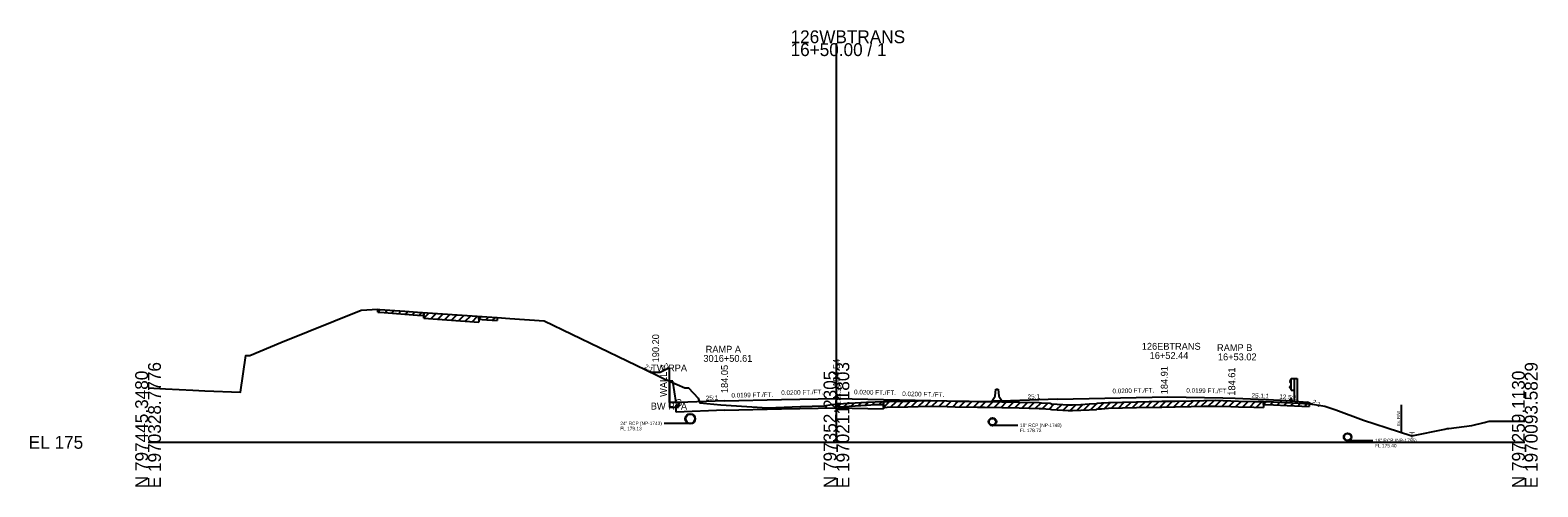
# Model space of a CAD drawing. Extents: x -6494 to 1970605, y -10 to 798140.
# Drawn here: x -25.7 to 302.8, y 8990.3 to 9089.8 of the extents above; entities that cross this region are included whole.
import ezdxf

# ---------------------------------------------------------------- set-up
doc = ezdxf.new("R2010")
doc.units = 0
for name, color, linetype in [('Default', 7, 'Continuous'), ('RD_EX_SU_Misc_TxCode', 7, 'Continuous'), ('RD_GPK_XS_Cell', 7, 'Continuous'), ('RD_Sketch1', 7, 'Continuous'), ('RD_XS_Base', 7, 'Continuous'), ('RD_XS_Box', 7, 'Continuous'), ('RD_XS_CurbTop', 7, 'Continuous'), ('RD_XS_EarthShd', 7, 'Continuous'), ('RD_XS_EwShp', 7, 'Continuous'), ('RD_XS_ExGround', 7, 'Continuous'), ('RD_XS_ExPaveRet', 7, 'Continuous'), ('RD_XS_ExRW', 7, 'Continuous'), ('RD_XS_GR', 7, 'Continuous'), ('RD_XS_MedBWall', 7, 'Continuous'), ('RD_XS_Misc_Line', 7, 'Continuous'), ('RD_XS_Pave', 7, 'Continuous'), ('RD_XS_PaveOvlay', 7, 'Continuous'), ('RD_XS_PaveShd', 7, 'Continuous'), ('RD_XS_Pipe', 7, 'Continuous'), ('RD_XS_TieSlope', 7, 'Continuous'), ('RD_XS_TX_Elev_EX', 7, 'Continuous'), ('RD_XS_TX_Elev_PR', 7, 'Continuous'), ('RD_XS_TX_Misc', 7, 'Continuous'), ('RD_XS_TX_Notes', 7, 'Continuous'), ('RD_XS_TX_Profile', 7, 'Continuous'), ('RD_XS_TX_ShdSlope', 7, 'Continuous'), ('RD_XS_TX_Slope', 7, 'Continuous'), ('RD_XS_TX_Station', 7, 'Continuous')]:
    doc.layers.add(name, color=color, linetype=linetype)

msp = doc.modelspace()

# ---------------------------------------------------------------- linework, layer by layer
at = {"layer": 'Default'}
for p, q in [((184, 9009.2), (184.58, 9010.03)), ((184, 9008.95), (184, 9009.2)), ((186, 9008.95), (184, 9008.95)), ((184.58, 9010.03), (184.75, 9011.61)), ((184.75, 9011.61), (185.25, 9011.61)), ((185.25, 9011.61), (185.42, 9010.03)), ((185.42, 9010.03), (186, 9009.2)), ((186, 9009.2), (186, 9008.95))]:
    msp.add_line(p, q, dxfattribs=at)
at = {"layer": 'RD_GPK_XS_Cell'}
for p, q in [((150, 9000), (150, 9086.93)), ((0, 9000), (150, 9000)), ((150, 9000), (300, 9000))]:
    msp.add_line(p, q, dxfattribs=at)
at = {"layer": 'RD_XS_Base'}
for p, q in [((115.61, 9008.09), (115.61, 9008.65)), ((246.93, 9008.72), (246.93, 9009.21)), ((115.11, 9008.07), (115.61, 9008.09)), ((115.11, 9006.59), (115.11, 9008.07)), ((125.62, 9007.01), (115.11, 9006.59)), ((125.62, 9007.01), (138, 9007.26)), ((138, 9007.26), (150, 9007.5)), ((150, 9007.5), (160.27, 9007.3))]:
    msp.add_line(p, q, dxfattribs=at)
at = {"layer": 'RD_XS_Box'}
for p, q in [((113.61, 9008.65), (113.61, 9016.2)), ((115.61, 9008.65), (113.61, 9008.65))]:
    msp.add_line(p, q, dxfattribs=at)
at = {"layer": 'RD_XS_CurbTop'}
for p, q in [((248.81, 9009.06), (249.06, 9009.52)), ((248.81, 9009.06), (249.27, 9009.03)), ((249.27, 9009.03), (249.21, 9009.46))]:
    msp.add_line(p, q, dxfattribs=at)
msp.add_ellipse((249.13, 9009.44), major_axis=(0, -0.131), ratio=0.686, start_param=1.762783, end_param=4.036677, dxfattribs=at)
at = {"layer": 'RD_XS_EarthShd'}
msp.add_line((246.93, 9009.21), (248.93, 9009.05), dxfattribs=at)
at = {"layer": 'RD_XS_ExGround'}
msp.add_lwpolyline([(0, 9011.84), (3.82, 9011.65), (9.76, 9011.34), (12.4, 9011.23), (20.16, 9010.91), (21.3, 9018.88), (22.14, 9018.9), (28.91, 9021.74), (46.44, 9028.78), (50.07, 9028.98), (50.5, 9028.94), (55.98, 9028.55), (58.71, 9028.36), (72.8, 9027.38), (73.79, 9027.31), (76.09, 9027.17), (78.84, 9026.97), (86.32, 9026.45), (110.4, 9014.85), (112.75, 9013.68), (113.07, 9013.58), (113.6, 9013.35), (116.99, 9011.89), (117.75, 9011.89), (119.86, 9009.65), (120.25, 9008.58), (124.78, 9008.19), (134.97, 9007.51), (142.2, 9007.8), (147.25, 9007.97), (148.99, 9008.22), (150.27, 9008.38), (156.55, 9008.72), (158.43, 9008.83), (161.04, 9008.88), (165.55, 9008.96), (167.83, 9009.02), (170.58, 9009.1), (174.13, 9009.03), (175.87, 9009), (180.71, 9008.91), (182.24, 9008.89), (189.82, 9008.74), (194.21, 9008.65), (194.68, 9008.62), (196.57, 9008.5), (196.85, 9008.39), (199.32, 9008.24), (200.48, 9008.17), (201.45, 9008.2), (203.22, 9008.27), (205.05, 9008.36), (206.64, 9008.43), (206.88, 9008.53), (207.74, 9008.58), (209.3, 9008.66), (215.42, 9008.8), (220.87, 9008.93), (223.84, 9008.99), (227.32, 9009.05), (230.08, 9009.11), (232.57, 9009.15), (235.96, 9009.05), (237.58, 9009), (240.96, 9008.91), (245.27, 9008.8), (248.2, 9008.65), (253.03, 9008.42), (254.17, 9008.24), (256.42, 9007.87), (258.82, 9007.08), (264.87, 9004.83), (272.44, 9002.37), (275.35, 9001.43), (282.56, 9002.88), (283.11, 9002.98), (283.45, 9003.02), (288.47, 9003.68), (291.12, 9004.33), (292.24, 9004.58), (300, 9004.58)], dxfattribs=at)
at = {"layer": 'RD_XS_ExPaveRet'}
for p, q in [((50.07, 9028.35), (50.07, 9028.98)), ((50.07, 9028.35), (50.5, 9028.32)), ((50.5, 9028.32), (55.98, 9027.92)), ((60.1, 9027.01), (60.1, 9028.26)), ((60.1, 9028.26), (60.1, 9027.64)), ((55.98, 9027.92), (58.71, 9027.73)), ((58.71, 9027.73), (60.1, 9027.64)), ((60.1, 9027.01), (72.08, 9026.18)), ((72.08, 9027.43), (72.08, 9026.18)), ((72.08, 9026.81), (72.08, 9027.43)), ((72.08, 9026.81), (72.8, 9026.76)), ((72.8, 9026.76), (73.79, 9026.69)), ((73.79, 9026.69), (76.09, 9026.54)), ((76.09, 9027.17), (76.09, 9026.54)), ((150.27, 9007.76), (150.27, 9008.38)), ((160.27, 9007.61), (160.27, 9008.86)), ((160.27, 9008.86), (160.27, 9008.24)), ((243.03, 9008.86), (243.03, 9007.61)), ((243.03, 9008.23), (243.03, 9008.86)), ((253.03, 9008.42), (253.03, 9007.79)), ((150.27, 9007.76), (156.55, 9008.1)), ((156.55, 9008.1), (158.43, 9008.21)), ((158.43, 9008.21), (160.27, 9008.24)), ((160.27, 9007.61), (161.04, 9007.63)), ((161.04, 9007.63), (165.55, 9007.71)), ((165.55, 9007.71), (167.83, 9007.77)), ((167.83, 9007.77), (170.58, 9007.85)), ((170.58, 9007.85), (174.13, 9007.78)), ((174.13, 9007.78), (175.87, 9007.75)), ((175.87, 9007.75), (180.71, 9007.66)), ((180.71, 9007.66), (182.24, 9007.64)), ((182.24, 9007.64), (189.82, 9007.49)), ((189.82, 9007.49), (194.21, 9007.4)), ((194.21, 9007.4), (194.68, 9007.37)), ((194.68, 9007.37), (196.57, 9007.25)), ((196.57, 9007.25), (196.85, 9007.14)), ((196.85, 9007.14), (199.32, 9006.99)), ((199.32, 9006.99), (200.48, 9006.92)), ((200.48, 9006.92), (201.45, 9006.95)), ((201.45, 9006.95), (203.22, 9007.02)), ((203.22, 9007.02), (205.05, 9007.11)), ((205.05, 9007.11), (206.64, 9007.18)), ((206.64, 9007.18), (206.88, 9007.28)), ((206.88, 9007.28), (207.74, 9007.33)), ((207.74, 9007.33), (209.3, 9007.41)), ((209.3, 9007.41), (215.42, 9007.55)), ((215.42, 9007.55), (220.87, 9007.68)), ((220.87, 9007.68), (223.84, 9007.74)), ((223.84, 9007.74), (227.32, 9007.8)), ((227.32, 9007.8), (230.08, 9007.86)), ((230.08, 9007.86), (232.57, 9007.9)), ((232.57, 9007.9), (235.96, 9007.8)), ((235.96, 9007.8), (237.58, 9007.75)), ((237.58, 9007.75), (240.96, 9007.66)), ((240.96, 9007.66), (243.03, 9007.61)), ((243.03, 9008.23), (245.27, 9008.17)), ((245.27, 9008.17), (248.2, 9008.03)), ((248.2, 9008.03), (253.03, 9007.79))]:
    msp.add_line(p, q, dxfattribs=at)
at = {"layer": 'RD_XS_ExRW'}
msp.add_line((273.04, 9008.17), (273.04, 9002.17), dxfattribs=at)
at = {"layer": 'RD_XS_GR'}
for p, q in [((249.08, 9013.77), (248.81, 9013.33)), ((248.81, 9013.33), (248.81, 9013.22)), ((248.81, 9013.22), (249.08, 9012.78)), ((248.81, 9012.07), (249.08, 9012.51)), ((248.81, 9011.96), (248.81, 9012.07)), ((249.08, 9011.52), (248.81, 9011.96)), ((249.08, 9013.93), (249.74, 9013.93)), ((249.08, 9011.36), (249.08, 9013.93)), ((249.74, 9013.93), (250.41, 9013.93)), ((249.74, 9013.93), (249.74, 9008.99)), ((250.41, 9013.93), (250.41, 9008.88)), ((249.08, 9011.36), (249.74, 9011.36))]:
    msp.add_line(p, q, dxfattribs=at)
at = {"layer": 'RD_XS_MedBWall'}
for p, q in [((114.36, 9013.32), (113.61, 9013.32)), ((113.61, 9013.32), (113.61, 9007.65)), ((115.11, 9008.65), (114.36, 9013.32)), ((115.61, 9008.65), (115.11, 9008.65)), ((115.61, 9007.65), (115.61, 9008.65)), ((113.61, 9007.65), (115.61, 9007.65))]:
    msp.add_line(p, q, dxfattribs=at)
at = {"layer": 'RD_XS_Misc_Line'}
for p, q in [((50.07, 9028.35), (50.65, 9028.93)), ((51.57, 9028.24), (52.16, 9028.82)), ((53.08, 9028.13), (53.66, 9028.72)), ((54.58, 9028.02), (55.17, 9028.61)), ((56.09, 9027.91), (56.68, 9028.5)), ((57.59, 9027.81), (58.18, 9028.39)), ((59.1, 9027.71), (59.69, 9028.29)), ((60.1, 9027.01), (61.27, 9028.18)), ((61.61, 9026.91), (62.78, 9028.08)), ((63.11, 9026.8), (64.28, 9027.97)), ((64.62, 9026.7), (65.79, 9027.87)), ((66.12, 9026.59), (67.29, 9027.76)), ((67.63, 9026.49), (68.8, 9027.66)), ((69.13, 9026.39), (70.3, 9027.55)), ((70.64, 9026.28), (71.81, 9027.45)), ((72.08, 9026.81), (72.67, 9027.39)), ((73.59, 9026.7), (74.18, 9027.29)), ((75.09, 9026.61), (75.68, 9027.19)), ((150.27, 9007.76), (150.94, 9008.42)), ((151.78, 9007.84), (152.44, 9008.5)), ((153.28, 9007.92), (153.95, 9008.58)), ((154.79, 9008), (155.45, 9008.67)), ((156.29, 9008.09), (156.96, 9008.75)), ((157.8, 9008.17), (158.46, 9008.83)), ((159.3, 9008.22), (159.94, 9008.86)), ((160.27, 9007.61), (161.55, 9008.89)), ((161.78, 9007.64), (163.06, 9008.91)), ((163.29, 9007.67), (164.56, 9008.94)), ((164.79, 9007.69), (166.07, 9008.97)), ((166.3, 9007.73), (167.59, 9009.02)), ((167.8, 9007.77), (169.09, 9009.06)), ((169.31, 9007.81), (170.59, 9009.1)), ((170.81, 9007.84), (172.04, 9009.07)), ((172.32, 9007.82), (173.55, 9009.04)), ((173.82, 9007.79), (175.05, 9009.02)), ((175.33, 9007.76), (176.56, 9008.99)), ((176.83, 9007.73), (178.06, 9008.96)), ((178.34, 9007.71), (179.57, 9008.93)), ((179.84, 9007.68), (181.07, 9008.91)), ((181.35, 9007.65), (182.58, 9008.88)), ((182.85, 9007.62), (184.08, 9008.85)), ((184.36, 9007.59), (185.59, 9008.82)), ((185.86, 9007.56), (187.09, 9008.79)), ((187.37, 9007.53), (188.6, 9008.76)), ((188.87, 9007.5), (190.1, 9008.73)), ((190.38, 9007.47), (191.61, 9008.7)), ((191.88, 9007.45), (193.11, 9008.67)), ((193.39, 9007.42), (194.6, 9008.63)), ((194.89, 9007.36), (196.07, 9008.54)), ((203.92, 9007.05), (205.24, 9008.36)), ((205.43, 9007.12), (206.82, 9008.51)), ((206.93, 9007.29), (208.26, 9008.6)), ((208.44, 9007.36), (209.75, 9008.67)), ((209.94, 9007.42), (211.23, 9008.7)), ((211.45, 9007.46), (212.73, 9008.74)), ((212.95, 9007.49), (214.24, 9008.77)), ((214.46, 9007.53), (215.74, 9008.81)), ((215.96, 9007.56), (217.25, 9008.85)), ((217.47, 9007.6), (218.76, 9008.88)), ((218.97, 9007.64), (220.26, 9008.92)), ((220.48, 9007.67), (221.76, 9008.95)), ((221.98, 9007.7), (223.26, 9008.98)), ((223.49, 9007.73), (224.77, 9009)), ((225, 9007.76), (226.27, 9009.03)), ((226.5, 9007.78), (227.78, 9009.06)), ((228.01, 9007.81), (229.29, 9009.09)), ((229.51, 9007.84), (230.79, 9009.12)), ((231.02, 9007.87), (232.29, 9009.14)), ((232.52, 9007.9), (233.74, 9009.11)), ((234.03, 9007.86), (235.24, 9009.07)), ((235.53, 9007.81), (236.75, 9009.02)), ((237.04, 9007.77), (238.26, 9008.98)), ((238.54, 9007.73), (239.76, 9008.94)), ((240.05, 9007.69), (241.27, 9008.9)), ((241.55, 9007.65), (242.77, 9008.86)), ((243.03, 9008.23), (243.64, 9008.84)), ((244.53, 9008.19), (245.15, 9008.8)), ((246.04, 9008.13), (246.64, 9008.73)), ((247.54, 9008.06), (248.14, 9008.66)), ((249.05, 9007.99), (249.65, 9008.58)), ((250.55, 9007.91), (251.15, 9008.51)), ((252.06, 9007.84), (252.66, 9008.44)), ((196.4, 9007.27), (197.48, 9008.35)), ((197.9, 9007.07), (199.09, 9008.25)), ((199.41, 9006.98), (200.6, 9008.17)), ((200.91, 9006.93), (202.21, 9008.23)), ((202.42, 9006.99), (203.73, 9008.29))]:
    msp.add_line(p, q, dxfattribs=at)
at = {"layer": 'RD_XS_Pave'}
for p, q in [((125.62, 9009.05), (138, 9009.3)), ((138, 9009.3), (150, 9009.54)), ((150, 9009.54), (174, 9009.06)), ((198.18, 9009.43), (222.19, 9009.91)), ((222.19, 9009.91), (234.19, 9009.67)), ((234.19, 9009.67), (236.9, 9009.61))]:
    msp.add_line(p, q, dxfattribs=at)
at = {"layer": 'RD_XS_PaveOvlay'}
for p, q in [((160.27, 9008.86), (161.04, 9008.88)), ((160.27, 9008.86), (160.27, 9007.3)), ((161.04, 9008.88), (165.55, 9008.96)), ((165.55, 9008.96), (167.83, 9009.02)), ((167.83, 9009.02), (170.58, 9009.1)), ((170.58, 9009.1), (174.13, 9009.03)), ((174.13, 9009.03), (175.87, 9009)), ((175.87, 9009), (180.71, 9008.91)), ((180.71, 9008.91), (182.24, 9008.89)), ((182.24, 9008.89), (189.82, 9008.74)), ((189.82, 9008.74), (194.21, 9008.65)), ((194.21, 9008.65), (194.68, 9008.62)), ((194.68, 9008.62), (196.57, 9008.5)), ((196.57, 9008.5), (196.85, 9008.39)), ((196.85, 9008.39), (199.32, 9008.24)), ((205.05, 9008.36), (206.64, 9008.43)), ((206.64, 9008.43), (206.88, 9008.53)), ((206.88, 9008.53), (207.74, 9008.58)), ((207.74, 9008.58), (209.3, 9008.66)), ((209.3, 9008.66), (215.42, 9008.8)), ((215.42, 9008.8), (220.87, 9008.93)), ((220.87, 9008.93), (223.84, 9008.99)), ((223.84, 9008.99), (227.32, 9009.05)), ((227.32, 9009.05), (230.08, 9009.11)), ((230.08, 9009.11), (232.57, 9009.15)), ((232.57, 9009.15), (235.96, 9009.05)), ((235.96, 9009.05), (237.58, 9009)), ((237.58, 9009), (240.96, 9008.91)), ((240.96, 9008.91), (243.03, 9008.86)), ((243.03, 9008.86), (245.27, 9008.8)), ((245.27, 9008.8), (246.93, 9008.72)), ((199.32, 9008.24), (200.48, 9008.17)), ((200.48, 9008.17), (201.45, 9008.2)), ((201.45, 9008.2), (203.22, 9008.27)), ((203.22, 9008.27), (205.05, 9008.36))]:
    msp.add_line(p, q, dxfattribs=at)
at = {"layer": 'RD_XS_PaveShd'}
for p, q in [((125.62, 9009.05), (115.61, 9008.65)), ((174, 9009.06), (183.89, 9008.86)), ((198.18, 9009.43), (183.89, 9008.86)), ((236.9, 9009.61), (246.93, 9009.21))]:
    msp.add_line(p, q, dxfattribs=at)
at = {"layer": 'RD_XS_Pipe'}
for p, q in [((117.49, 9004.13), (112.49, 9004.13)), ((184.5, 9003.72), (189.5, 9003.72)), ((261.88, 9000.4), (266.88, 9000.4))]:
    msp.add_line(p, q, dxfattribs=at)
for centre, radius in [((118.15, 9005.13), 1.1), ((118.15, 9005.13), 1), ((184, 9004.47), 0.85), ((184, 9004.47), 0.75), ((261.38, 9001.15), 0.85), ((261.38, 9001.15), 0.75)]:
    msp.add_circle(centre, radius, dxfattribs=at)
at = {"layer": 'RD_XS_TieSlope'}
for p, q in [((107.61, 9016.2), (109.61, 9015.2)), ((111.61, 9015.2), (109.61, 9015.2)), ((113.61, 9016.2), (111.61, 9015.2)), ((248.93, 9009.05), (252.68, 9008.75)), ((253.5, 9008.34), (252.68, 9008.75))]:
    msp.add_line(p, q, dxfattribs=at)

# ---------------------------------------------------------------- texts
at = {"layer": 'RD_EX_SU_Misc_TxCode'}
msp.add_text('G', height=1.5, dxfattribs=at).set_placement((114.86, 9007.9))
at = {"layer": 'RD_GPK_XS_Cell'}
for s, p in [('126WBTRANS', (140, 9086.93)), ('16+50.00 / 1', (140, 9084.13)), ('EL 175', (-26, 8998.6))]:
    msp.add_text(s, height=2.8, dxfattribs=at).set_placement(p)
for s, p in [('N 797445.3480', (0, 8990)), ('E 1970328.7776', (2.8, 8990)), ('N 797352.2305', (150, 8990)), ('E 1970211.1803', (152.8, 8990)), ('N 797259.1130', (300, 8990)), ('E 1970093.5829', (302.8, 8990))]:
    msp.add_text(s, height=2.8, rotation=90, dxfattribs=at).set_placement(p)
at = {"layer": 'RD_Sketch1'}
msp.add_text('T', height=1.5, dxfattribs=at).set_placement((274.8, 9000.68))
at = {"layer": 'RD_XS_EwShp'}
for s, p in [('TW RPA', (109.64, 9015.45)), ('BW RPA', (109.54, 9007.13))]:
    msp.add_text(s, height=1.5, dxfattribs=at).set_placement(p)
at = {"layer": 'RD_XS_ExRW'}
msp.add_text('Ex. R/W ', height=0.65, rotation=90, dxfattribs=at).set_placement((272.79, 9003.56))
at = {"layer": 'RD_XS_Pipe'}
for s, p in [('24" RCP (NP-1743)', (102.9, 9003.75)), ('FL 179.13', (102.9, 9002.63)), ('18" RCP (NP-1748)', (190, 9003.35)), ('FL 178.72', (190, 9002.22)), ('18" RCP (NP-1755)', (267.38, 9000.03)), ('FL 175.40', (267.38, 8998.9))]:
    msp.add_text(s, height=0.75, dxfattribs=at).set_placement(p)
at = {"layer": 'RD_XS_TX_Elev_EX'}
msp.add_text('183.35', height=1, rotation=90, dxfattribs=at).set_placement((151, 9008.35))
at = {"layer": 'RD_XS_TX_Elev_PR'}
for s, p in [('184.05', (126.37, 9010.73)), ('184.54', (150.75, 9012.06)), (' 184.91', (222.19, 9009.91)), (' 184.61', (236.9, 9009.61))]:
    msp.add_text(s, height=1.5, rotation=90, dxfattribs=at).set_placement(p)
at = {"layer": 'RD_XS_TX_Misc'}
msp.add_text('190.20', height=1.5, rotation=90, dxfattribs=at).set_placement((111.36, 9017.42))
at = {"layer": 'RD_XS_TX_Notes'}
msp.add_text('WALL', height=1.5, rotation=90, dxfattribs=at).set_placement((113.05, 9009.9))
at = {"layer": 'RD_XS_TX_Profile'}
for s, rotation, p in [('25:1', 2.2905, (191.68, 9009.42)), ('25.1:1', 357.7148, (240.44, 9009.72))]:
    msp.add_text(s, height=1, rotation=rotation, dxfattribs=at).set_placement(p)
at = {"layer": 'RD_XS_TX_ShdSlope'}
msp.add_text('12.5:1', height=1, rotation=355.4368, dxfattribs=at).set_placement((246.47, 9009.5))
at = {"layer": 'RD_XS_TX_Slope'}
for s, rotation, p in [('2:1', 333.4349, (108.06, 9016.18)), ('2:1', 26.5651, (112.01, 9015.71)), ('0.0200 FT./FT.', 1.1465, (210.16, 9010.67)), ('0.0199 FT./FT.', 358.8579, (226.23, 9010.83)), ('25:1', 2.2878, (121.55, 9009.14)), ('0.0199 FT./FT.', 1.1405, (127.12, 9009.74)), ('0.0200 FT./FT.', 1.1458, (137.98, 9010.3)), ('0.0200 FT./FT.', 358.8542, (153.83, 9010.47)), ('0.0200 FT./FT.', 358.8542, (164.33, 9010.08)), ('2:1', 333.4349, (253.53, 9008.49))]:
    msp.add_text(s, height=1, rotation=rotation, dxfattribs=at).set_placement(p)
at = {"layer": 'RD_XS_TX_Station'}
for s, p in [('126EBTRANS', (216.54, 9020.16)), ('3016+50.61', (121.01, 9017.53)), ('RAMP A', (121.51, 9019.53)), ('16+52.44', (218.26, 9018.16)), ('RAMP B', (232.94, 9019.86)), ('16+53.02', (233.13, 9017.86))]:
    msp.add_text(s, height=1.5, dxfattribs=at).set_placement(p)

doc.saveas('drawing.dxf')
